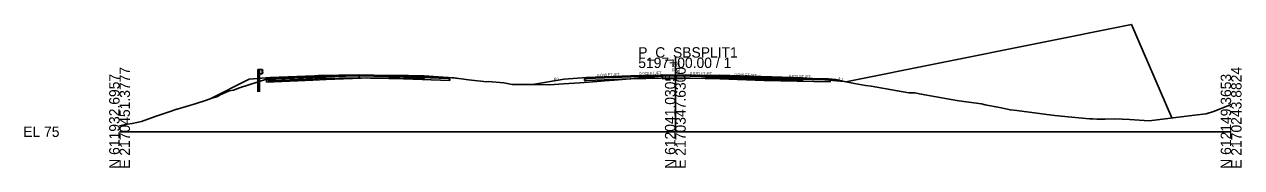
# Model space of a CAD drawing. Extents: x -26 to 1303, y -3010 to 12033.
# Drawn here: x 974.3 to 1302.8, y 490.3 to 529 of the extents above; entities that cross this region are included whole.
import ezdxf

# ---------------------------------------------------------------- set-up
doc = ezdxf.new("R2010")
doc.units = 0
for name, color, linetype in [('RD_GPK_XS_Cell', 7, 'Continuous'), ('RD_PD_Final_TrvlWay', 7, 'Continuous'), ('RD_Sketch10', 7, 'Continuous'), ('RD_XS_Base', 7, 'Continuous'), ('RD_XS_ExGround', 7, 'Continuous'), ('RD_XS_ExPaveRet', 7, 'Continuous'), ('RD_XS_GR', 7, 'Continuous'), ('RD_XS_Greenside', 7, 'Continuous'), ('RD_XS_Pave', 7, 'Continuous'), ('RD_XS_PaveOvlay_CP', 7, 'Continuous'), ('RD_XS_TieSlope', 7, 'Continuous'), ('RD_XS_TX_Elev_EX', 7, 'Continuous'), ('RD_XS_TX_Elev_PR', 7, 'Continuous'), ('RD_XS_TX_Slope', 7, 'Continuous')]:
    doc.layers.add(name, color=color, linetype=linetype)

msp = doc.modelspace()

# ---------------------------------------------------------------- linework, layer by layer
at = {"layer": 'RD_GPK_XS_Cell'}
for p, q in [((1150, 500), (1150, 520)), ((1000, 500), (1150, 500)), ((1150, 500), (1300, 500))]:
    msp.add_line(p, q, dxfattribs=at)
at = {"layer": 'RD_PD_Final_TrvlWay'}
msp.add_lwpolyline([(1037.79, 510.8), (1037.79, 514.41), (1037.29, 514.37), (1037.29, 510.8)], dxfattribs=at)
at = {"layer": 'RD_Sketch10'}
msp.add_lwpolyline([(1196.02, 513.45), (1273.09, 528.97), (1284.02, 503.73)], dxfattribs=at)
at = {"layer": 'RD_XS_Base'}
for p, q in [((1040.15, 513.83), (1040.15, 514.3)), ((1040.15, 514.3), (1040.19, 514.3)), ((1040.15, 513.8), (1040.15, 513.83)), ((1040.19, 513.8), (1040.15, 513.8)), ((1040.19, 514.3), (1040.65, 514.32)), ((1040.65, 513.82), (1040.19, 513.8)), ((1040.65, 514.32), (1041.51, 514.35)), ((1041.51, 513.85), (1040.65, 513.82)), ((1041.51, 514.35), (1052.65, 514.8)), ((1052.65, 514.3), (1041.51, 513.85)), ((1052.65, 514.8), (1053.68, 514.82)), ((1053.68, 514.32), (1052.65, 514.3)), ((1053.68, 514.82), (1064.65, 515.04)), ((1064.65, 514.54), (1053.68, 514.32)), ((1064.65, 515.04), (1064.65, 515.2)), ((1064.65, 515.2), (1064.65, 514.54)), ((1064.65, 515.04), (1064.65, 514.54)), ((1076.65, 514.8), (1064.65, 515.04)), ((1064.65, 515.04), (1064.65, 515.04)), ((1064.65, 514.54), (1064.65, 514.54)), ((1064.65, 514.54), (1064.65, 514.54)), ((1064.65, 514.54), (1076.65, 514.3)), ((1088.65, 514.32), (1076.65, 514.8)), ((1076.65, 514.3), (1089.15, 513.8)), ((1078.65, 514.72), (1078.65, 514.72)), ((1078.65, 514.22), (1078.65, 514.22)), ((1089.15, 514.3), (1088.65, 514.32)), ((1088.65, 514.32), (1088.65, 514.32)), ((1089.15, 513.8), (1089.15, 514.3)), ((1089.15, 514.3), (1089.15, 514.3)), ((1089.15, 513.8), (1089.15, 513.8)), ((1089.15, 513.8), (1089.15, 513.8)), ((1125.5, 514.3), (1126, 514.32)), ((1125.5, 513.8), (1125.5, 514.3)), ((1125.5, 514.3), (1125.5, 514.3)), ((1126, 513.82), (1125.5, 513.8)), ((1125.5, 513.8), (1125.5, 513.8)), ((1125.5, 513.8), (1125.5, 513.8)), ((1126, 514.32), (1138, 514.8)), ((1126, 514.32), (1126, 514.32)), ((1138, 514.3), (1126, 513.82)), ((1126, 513.82), (1126, 513.82)), ((1136, 514.72), (1136, 514.72)), ((1136, 514.22), (1136, 514.22)), ((1138, 514.8), (1150, 515.04)), ((1150, 514.54), (1138, 514.3)), ((1150, 515.04), (1150, 515.2)), ((1150, 515.2), (1150, 514.54)), ((1150, 515.04), (1150, 515.04)), ((1162, 514.8), (1150, 515.04)), ((1150, 515.04), (1150, 515.04)), ((1150, 515.04), (1150, 514.54)), ((1150, 514.54), (1150, 514.54)), ((1150, 514.54), (1162, 514.3)), ((1150, 514.54), (1150, 514.54)), ((1174, 514.32), (1162, 514.8)), ((1162, 514.8), (1162, 514.8)), ((1162, 514.3), (1162, 514.3)), ((1162, 514.3), (1174, 513.82)), ((1191.3, 513.97), (1174, 514.32)), ((1174, 514.32), (1174, 514.32)), ((1174, 513.82), (1174, 513.82)), ((1174, 513.82), (1191.8, 513.46)), ((1191.8, 513.96), (1191.3, 513.97)), ((1191.3, 513.97), (1191.3, 513.97)), ((1191.8, 513.46), (1191.8, 513.96)), ((1191.8, 513.96), (1191.8, 513.96)), ((1191.8, 513.46), (1191.8, 513.46)), ((1191.8, 513.46), (1191.8, 513.46))]:
    msp.add_line(p, q, dxfattribs=at)
at = {"layer": 'RD_XS_ExGround'}
msp.add_lwpolyline([(1000, 501.58), (1002.05, 502.01), (1003.37, 502.19), (1005.96, 502.76), (1009.6, 504.09), (1013.14, 505.28), (1015.43, 506.08), (1015.57, 506.08), (1020.4, 507.56), (1023.44, 508.51), (1024.95, 509.05), (1026.51, 509.49), (1026.96, 509.82), (1029.62, 510.99), (1030.75, 511.22), (1032.35, 511.81), (1039.67, 514.15), (1055.76, 514.81), (1066.52, 515.25), (1075.61, 515.17), (1082.19, 515.1), (1087.37, 514.72), (1090.3, 514.5), (1094.2, 514), (1099.15, 513.5), (1099.45, 513.52), (1103.71, 513.2), (1106, 512.78), (1111.52, 512.74), (1116.07, 512.68), (1119.85, 512.95), (1124.25, 513.23), (1128.92, 513.52), (1130.88, 513.74), (1133.51, 513.91), (1146.55, 515), (1152.2, 515.1), (1161.86, 515.27), (1181.71, 514.62), (1184.31, 514.54), (1186.09, 514.37), (1189.23, 514.09), (1195.67, 513.51), (1198.33, 513.04), (1201.35, 512.5), (1202.81, 512.26), (1209.93, 511.03), (1212.99, 510.51), (1213.85, 510.5), (1214.64, 510.48), (1216.37, 510.17), (1224.4, 508.71), (1226.55, 508.34), (1232.67, 507.48), (1233.6, 507.26), (1237.49, 506.51), (1240.42, 505.87), (1242.17, 505.71), (1244.15, 505.48), (1245.57, 505.28), (1251.6, 504.5), (1254.14, 504.22), (1261.79, 503.5), (1262.72, 503.45), (1263.72, 503.41), (1266.04, 503.4), (1268.64, 503.46), (1272.56, 503.29), (1277.9, 502.96), (1290.14, 504.5), (1293.28, 504.81), (1295.23, 505.47), (1300, 507.37)], dxfattribs=at)
at = {"layer": 'RD_XS_ExPaveRet'}
for points in [[(1075.61, 515.17), (1067.71, 515.24), (1066.52, 515.25), (1065.18, 515.19), (1055.76, 514.81), (1052.18, 514.66), (1039.67, 514.15), (1039.67, 513.5), (1039.67, 513.4), (1052.18, 513.91), (1055.76, 514.06), (1065.18, 514.44), (1066.52, 514.5), (1067.71, 514.49), (1075.61, 514.42), (1077.94, 514.39), (1082.19, 514.35), (1082.19, 514.53), (1082.19, 515.1), (1077.94, 515.14), (1075.61, 515.17)], [(1075.61, 515.17), (1067.71, 515.24), (1066.52, 515.25), (1065.18, 515.19), (1055.76, 514.81), (1052.18, 514.66), (1039.67, 514.15), (1039.67, 513.5), (1039.67, 513.4), (1052.18, 513.91), (1055.76, 514.06), (1065.18, 514.44), (1066.52, 514.5), (1067.71, 514.49), (1075.61, 514.42), (1077.94, 514.39), (1082.19, 514.35), (1082.19, 514.53), (1082.19, 515.1), (1077.94, 515.14), (1075.61, 515.17)], [(1184.31, 514.54), (1184.31, 514.54), (1184.31, 513.79), (1184.31, 513.79), (1181.71, 513.87), (1181.71, 513.87), (1161.86, 514.52), (1161.86, 514.52), (1152.2, 514.35), (1152.2, 514.35), (1146.55, 514.25), (1146.55, 514.25), (1146.55, 514.25), (1146.55, 515), (1146.55, 515), (1152.2, 515.1), (1152.2, 515.1), (1161.86, 515.27), (1161.86, 515.27), (1181.71, 514.62), (1181.71, 514.62), (1184.31, 514.54), (1184.31, 514.54)], [(1184.31, 514.54), (1181.71, 514.62), (1161.86, 515.27), (1152.2, 515.1), (1146.55, 515), (1146.55, 514.25), (1152.2, 514.35), (1161.86, 514.52), (1181.71, 513.87), (1184.31, 513.79), (1184.31, 513.79), (1184.31, 514.54), (1184.31, 514.54)]]:
    msp.add_lwpolyline(points, dxfattribs=at)
at = {"layer": 'RD_XS_GR'}
for p, q in [((1037.29, 514.37), (1037.29, 516.8)), ((1037.29, 516.8), (1037.54, 516.8)), ((1037.54, 516.8), (1037.79, 516.8)), ((1037.79, 516.8), (1037.79, 514.41)), ((1037.79, 515.64), (1037.79, 516.8)), ((1037.79, 516.8), (1038.46, 516.8)), ((1038.46, 516.8), (1038.46, 515.64)), ((1038.71, 516.53), (1038.46, 516.8)), ((1038.46, 516.8), (1038.46, 515.72)), ((1038.46, 516.22), (1038.48, 516.24)), ((1038.71, 515.95), (1038.46, 516.22)), ((1038.48, 516.24), (1038.73, 516.51)), ((1038.48, 515.66), (1038.73, 515.93)), ((1038.73, 516.51), (1038.71, 516.53)), ((1038.73, 515.93), (1038.71, 515.95)), ((1037.79, 514.41), (1037.29, 514.37)), ((1038.46, 515.64), (1037.79, 515.64)), ((1038.46, 515.72), (1038.46, 515.64)), ((1038.46, 515.64), (1038.48, 515.66))]:
    msp.add_line(p, q, dxfattribs=at)
at = {"layer": 'RD_XS_Greenside'}
for p, q in [((1034.98, 514.18), (1024.25, 508.82)), ((1090.65, 514.48), (1091.24, 514.38)), ((1120, 514.16), (1111.49, 512.74)), ((1193.3, 514.13), (1196.02, 513.45))]:
    msp.add_line(p, q, dxfattribs=at)
at = {"layer": 'RD_XS_Pave'}
for p, q in [((1041.51, 514.67), (1040.65, 514.64)), ((1040.65, 514.64), (1040.65, 514.49)), ((1041.51, 514.51), (1040.65, 514.48)), ((1040.65, 514.48), (1041.51, 514.51)), ((1040.65, 514.49), (1040.65, 514.48)), ((1040.65, 514.48), (1040.65, 514.33)), ((1040.65, 514.32), (1041.51, 514.35)), ((1040.65, 514.33), (1040.65, 514.32)), ((1052.65, 515.12), (1041.51, 514.67)), ((1052.65, 514.96), (1041.51, 514.51)), ((1041.51, 514.51), (1052.65, 514.96)), ((1041.51, 514.35), (1052.65, 514.8)), ((1053.68, 515.14), (1052.65, 515.12)), ((1053.68, 514.98), (1052.65, 514.96)), ((1052.65, 514.96), (1053.68, 514.98)), ((1052.65, 514.8), (1053.68, 514.82)), ((1064.65, 515.36), (1053.68, 515.14)), ((1064.65, 515.2), (1053.68, 514.98)), ((1053.68, 514.98), (1064.65, 515.2)), ((1053.68, 514.82), (1064.65, 515.04)), ((1076.65, 515.12), (1064.65, 515.36)), ((1064.65, 515.04), (1064.65, 515.2)), ((1064.65, 515.2), (1076.65, 514.96)), ((1076.65, 514.96), (1064.65, 515.2)), ((1064.65, 515.2), (1064.65, 515.04)), ((1064.65, 515.04), (1064.65, 515.04)), ((1064.65, 515.04), (1064.65, 515.04)), ((1064.65, 515.04), (1076.65, 514.8)), ((1088.65, 514.64), (1076.65, 515.12)), ((1076.65, 514.96), (1088.65, 514.48)), ((1088.65, 514.48), (1076.65, 514.96)), ((1076.65, 514.8), (1088.65, 514.32)), ((1078.65, 515.04), (1078.65, 515.04)), ((1078.65, 514.88), (1078.65, 514.88)), ((1078.65, 514.88), (1078.65, 514.88)), ((1078.65, 514.72), (1078.65, 514.72)), ((1088.65, 514.48), (1088.65, 514.64)), ((1088.65, 514.64), (1088.65, 514.64)), ((1088.65, 514.48), (1088.65, 514.48)), ((1088.65, 514.48), (1088.65, 514.48)), ((1088.65, 514.32), (1088.65, 514.48)), ((1088.65, 514.48), (1088.65, 514.48)), ((1088.65, 514.32), (1088.65, 514.32)), ((1088.65, 514.32), (1088.65, 514.32)), ((1138, 515.12), (1126, 514.64)), ((1138, 514.96), (1126, 514.48)), ((1126, 514.48), (1138, 514.96)), ((1126, 514.32), (1138, 514.8)), ((1126, 514.64), (1126, 514.64)), ((1126, 514.64), (1126, 514.48)), ((1126, 514.48), (1126, 514.48)), ((1126, 514.48), (1126, 514.32)), ((1126, 514.48), (1126, 514.48)), ((1126, 514.48), (1126, 514.48)), ((1126, 514.32), (1126, 514.32)), ((1126, 514.32), (1126, 514.32)), ((1136, 515.04), (1136, 515.04)), ((1136, 514.88), (1136, 514.88)), ((1136, 514.88), (1136, 514.88)), ((1136, 514.72), (1136, 514.72)), ((1150, 515.36), (1138, 515.12)), ((1150, 515.2), (1138, 514.96)), ((1138, 514.96), (1150, 515.2)), ((1138, 514.8), (1150, 515.04)), ((1162, 515.12), (1150, 515.36)), ((1150, 515.04), (1150, 515.2)), ((1150, 515.2), (1162, 514.96)), ((1162, 514.96), (1150, 515.2)), ((1150, 515.2), (1150, 515.2)), ((1150, 515.2), (1150, 515.04)), ((1150, 515.04), (1150, 515.04)), ((1150, 515.04), (1150, 515.04)), ((1150, 515.04), (1150, 515.04)), ((1150, 515.04), (1162, 514.8)), ((1174, 514.64), (1162, 515.12)), ((1162, 515.12), (1162, 515.12)), ((1162, 514.96), (1162, 514.96)), ((1162, 514.96), (1174, 514.48)), ((1174, 514.48), (1162, 514.96)), ((1162, 514.96), (1162, 514.96)), ((1162, 514.8), (1162, 514.8)), ((1162, 514.8), (1174, 514.32)), ((1191.3, 514.29), (1174, 514.64)), ((1174, 514.64), (1174, 514.64)), ((1174, 514.48), (1174, 514.48)), ((1174, 514.48), (1191.3, 514.13)), ((1191.3, 514.13), (1174, 514.48)), ((1174, 514.48), (1174, 514.48)), ((1174, 514.32), (1174, 514.32)), ((1174, 514.32), (1191.3, 513.97)), ((1191.3, 514.13), (1191.3, 514.29)), ((1191.3, 514.29), (1191.3, 514.29)), ((1191.3, 514.13), (1191.3, 514.13)), ((1191.3, 514.13), (1191.3, 514.13)), ((1191.3, 513.97), (1191.3, 514.13)), ((1191.3, 514.13), (1191.3, 514.13)), ((1191.3, 513.97), (1191.3, 513.97)), ((1191.3, 513.97), (1191.3, 513.97))]:
    msp.add_line(p, q, dxfattribs=at)
at = {"layer": 'RD_XS_PaveOvlay_CP'}
for p, q in [((1040.65, 514.64), (1052.65, 515.12)), ((1052.65, 515.12), (1064.65, 515.36)), ((1064.65, 515.36), (1076.65, 515.12)), ((1076.65, 515.12), (1088.65, 514.64)), ((1138, 515.12), (1126, 514.64)), ((1126, 514.64), (1126, 514.64)), ((1136, 515.04), (1136, 515.04)), ((1150, 515.36), (1138, 515.12)), ((1162, 515.12), (1150, 515.36)), ((1174, 514.64), (1162, 515.12)), ((1162, 515.12), (1162, 515.12)), ((1191.3, 514.29), (1174, 514.64)), ((1174, 514.64), (1174, 514.64)), ((1191.3, 514.29), (1191.3, 514.29))]:
    msp.add_line(p, q, dxfattribs=at)
at = {"layer": 'RD_XS_TieSlope'}
for p, q in [((1040.65, 514.64), (1034.98, 514.18)), ((1088.65, 514.64), (1090.65, 514.48)), ((1126, 514.64), (1120, 514.16)), ((1191.3, 514.29), (1193.3, 514.13))]:
    msp.add_line(p, q, dxfattribs=at)

# ---------------------------------------------------------------- texts
at = {"layer": 'RD_GPK_XS_Cell'}
for s, p in [('P_C_SBSPLIT1', (1140, 520)), ('5197+00.00 / 1', (1140, 517.2)), ('EL 75', (974, 498.6))]:
    msp.add_text(s, height=2.8, dxfattribs=at).set_placement(p)
for s, p in [('E 2170451.3777', (1002.8, 490)), ('E 2170347.6300', (1152.8, 490)), ('E 2170243.8824', (1302.8, 490)), ('N 611932.6957', (1000, 490)), ('N 612041.0305', (1150, 490)), ('N 612149.3653', (1300, 490))]:
    msp.add_text(s, height=2.8, rotation=90, dxfattribs=at).set_placement(p)
at = {"layer": 'RD_XS_TX_Elev_EX'}
msp.add_text('90.06', height=0.6, rotation=90, dxfattribs=at).set_placement((1149.7, 516.27))
at = {"layer": 'RD_XS_TX_Elev_PR'}
msp.add_text('90.36', height=1, rotation=90, dxfattribs=at).set_placement((1151.29, 515.59))
at = {"layer": 'RD_XS_TX_Slope'}
for s, rotation, p in [('0.040 FT./FT.', 2.2906, (1128.93, 514.85)), ('0.020 FT./FT.', 1.1458, (1140.27, 515.33)), ('0.020 FT./FT.', 358.8542, (1153.94, 515.38)), ('0.040 FT./FT.', 357.7094, (1165.94, 515.06)), ('6:1', 9.4642, (1117.27, 513.76)), ('0.020 FT./FT.', 358.8542, (1180.59, 514.6)), ('4:1', 345.9638, (1193.84, 514.06))]:
    msp.add_text(s, height=0.75, rotation=rotation, dxfattribs=at).set_placement(p)

doc.saveas('drawing.dxf')
